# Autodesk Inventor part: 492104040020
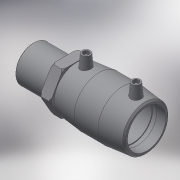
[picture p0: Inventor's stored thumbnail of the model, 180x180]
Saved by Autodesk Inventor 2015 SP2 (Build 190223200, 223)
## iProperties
Created: 2017-06
Part Number: 492104040020
Material: Generic
Description: PLASSON Male Transition Coupler 40 x 2"
Document SubType Name: Modeling
Designer: KIM
Mass: 367.656 g
Surface Area: 644.797 cm^2
Volume: 367.656 cm^3
Density: 1 g/cm^3
Appearance: Default
Author: KIM
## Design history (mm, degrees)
derived "492104.ipt"
feature "Solid1::492104.ipt"
tag "TaggingFeature1"
body "Solid1"
other parameters: "d0" = 119, "d2" = 69, "d3" = 44, "d4" = 39.66667, "d5" = 62.1, "d6" = 38, "d8" = 168 deg, "d10" = 17.6, "d11" = 5.86667, "d29" = 59, "d30" = 14, "d31" = 41.65, "d34" = 5 deg, "d41" = 4, "d42" = 14, "d43" = 0, "d48" = 3, "d49" = 0, "d57" = 29, "d58" = 59.614, "d59" = 47.6912, "d60" = 36.9, "d61" = 69, "d62" = 1.19228, "d65" = 2.07, "d70" = 0.1, "d71" = 41, "d72" = 10.25, "d73" = 17.6, "d75" = 0, "L_1" = 44, "D_1" = 69, "A_" = 59, "d_2" = 12, "L_2" = 41, "D_" = 29, "R_" = 59.614
